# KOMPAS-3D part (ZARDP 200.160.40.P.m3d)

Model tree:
1. Поверхность без истории:1
2. Поверхность без истории:2
3. Поверхность без истории:3
4. Поверхность без истории:4
5. Поверхность без истории:5
6. Поверхность без истории:6
7. Поверхность без истории:7
8. Поверхность без истории:8
9. Поверхность без истории:9
10. Поверхность без истории:10
11. Поверхность без истории:11
12. Поверхность без истории:12
13. Поверхность без истории:13
14. Поверхность без истории:14
15. Поверхность без истории:15
16. Поверхность без истории:16
17. Поверхность без истории:17
18. Поверхность без истории:18
19. Поверхность без истории:19
20. Поверхность без истории:20
21. Поверхность без истории:21
22. Поверхность без истории:22
23. Поверхность без истории:23
24. Поверхность без истории:24
25. Поверхность без истории:25
26. Поверхность без истории:26
27. Поверхность без истории:27
28. Поверхность без истории:28
29. Поверхность без истории:29
30. Поверхность без истории:30
31. Поверхность без истории:31
32. Поверхность без истории:32
33. Поверхность без истории:33
34. Поверхность без истории:34
35. Поверхность без истории:35
36. Поверхность без истории:36
37. Поверхность без истории:37
38. Поверхность без истории:38
39. Поверхность без истории:39
40. Поверхность без истории:40
41. Поверхность без истории:41
42. Поверхность без истории:42
43. Поверхность без истории:43
44. Поверхность без истории:44
45. Поверхность без истории:45
46. Поверхность без истории:46
47. Поверхность без истории:47
48. Поверхность без истории:48
49. Поверхность без истории:49
50. Поверхность без истории:50
51. Поверхность без истории:51
52. Поверхность без истории:52
53. Поверхность без истории:53
54. Поверхность без истории:54
55. Поверхность без истории:55
56. Поверхность без истории:56
57. Поверхность без истории:57
58. Поверхность без истории:58
59. Поверхность без истории:59
60. Поверхность без истории:60
61. Поверхность без истории:61
62. Поверхность без истории:62
63. Поверхность без истории:63
64. Поверхность без истории:64
65. Поверхность без истории:65
66. Поверхность без истории:66
67. Поверхность без истории:67
68. Поверхность без истории:68
69. Поверхность без истории:69
70. Поверхность без истории:70
71. Поверхность без истории:71
72. Поверхность без истории:72
73. Поверхность без истории:73
74. Поверхность без истории:74
75. Поверхность без истории:75
76. Поверхность без истории:76
77. Поверхность без истории:77
78. Поверхность без истории:78
79. Поверхность без истории:79
80. Поверхность без истории:80
81. Поверхность без истории:81
82. Поверхность без истории:82
83. Поверхность без истории:83
84. Поверхность без истории:84
85. Поверхность без истории:85
86. Поверхность без истории:86
87. Поверхность без истории:87
88. Поверхность без истории:88
89. Поверхность без истории:89
90. Поверхность без истории:90
91. Поверхность без истории:91
92. Поверхность без истории:92
93. Поверхность без истории:93
94. Поверхность без истории:94
95. Поверхность без истории:95
96. Поверхность без истории:96
97. Поверхность без истории:97
98. Поверхность без истории:98
99. Поверхность без истории:99
100. Поверхность без истории:100
101. Поверхность без истории:101
102. Поверхность без истории:102
103. Поверхность без истории:103
104. Поверхность без истории:104
105. Поверхность без истории:105
106. Поверхность без истории:106
107. Поверхность без истории:107
108. Поверхность без истории:108
109. Поверхность без истории:109
110. Поверхность без истории:110
111. Поверхность без истории:111
112. Поверхность без истории:112
113. Поверхность без истории:113
114. Поверхность без истории:114
115. Поверхность без истории:115
116. Поверхность без истории:116
117. Поверхность без истории:117
118. Поверхность без истории:118
119. Поверхность без истории:119
120. Поверхность без истории:120
121. Поверхность без истории:121
122. Поверхность без истории:122
123. Поверхность без истории:123
124. Поверхность без истории:124
125. Поверхность без истории:125
126. Поверхность без истории:126
127. Поверхность без истории:127
128. Поверхность без истории:128
129. Поверхность без истории:129
130. Поверхность без истории:130
131. Поверхность без истории:131
132. Поверхность без истории:132
133. Поверхность без истории:133
134. Поверхность без истории:134
135. Поверхность без истории:135

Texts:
  ЗАРДП 200.160.40-ХХ.Р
